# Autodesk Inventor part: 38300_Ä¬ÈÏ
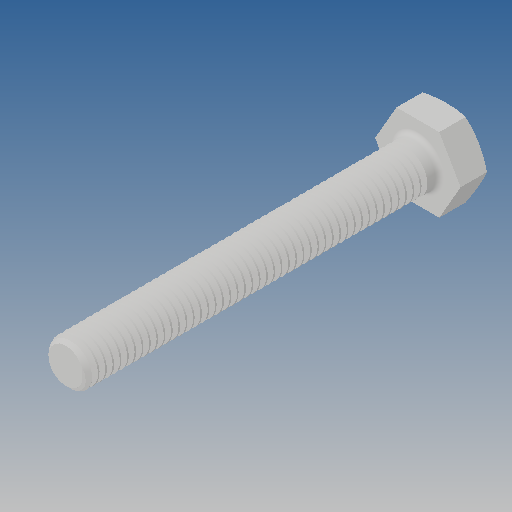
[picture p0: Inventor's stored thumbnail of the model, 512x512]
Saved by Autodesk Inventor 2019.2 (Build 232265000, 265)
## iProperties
Created: 2010-06
Part Number: 38300_Ä¬ÈÏ
Material: Ogólny
Document SubType Name: Modeling
Designer: CADENGINEERING4
Density: 1 g/cm^3
Appearance: Domyślna
Author: CADENGINEERING4
Revision Number: ÈÎºÎ
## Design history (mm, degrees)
feature "NONE"
node "Bryła1"
